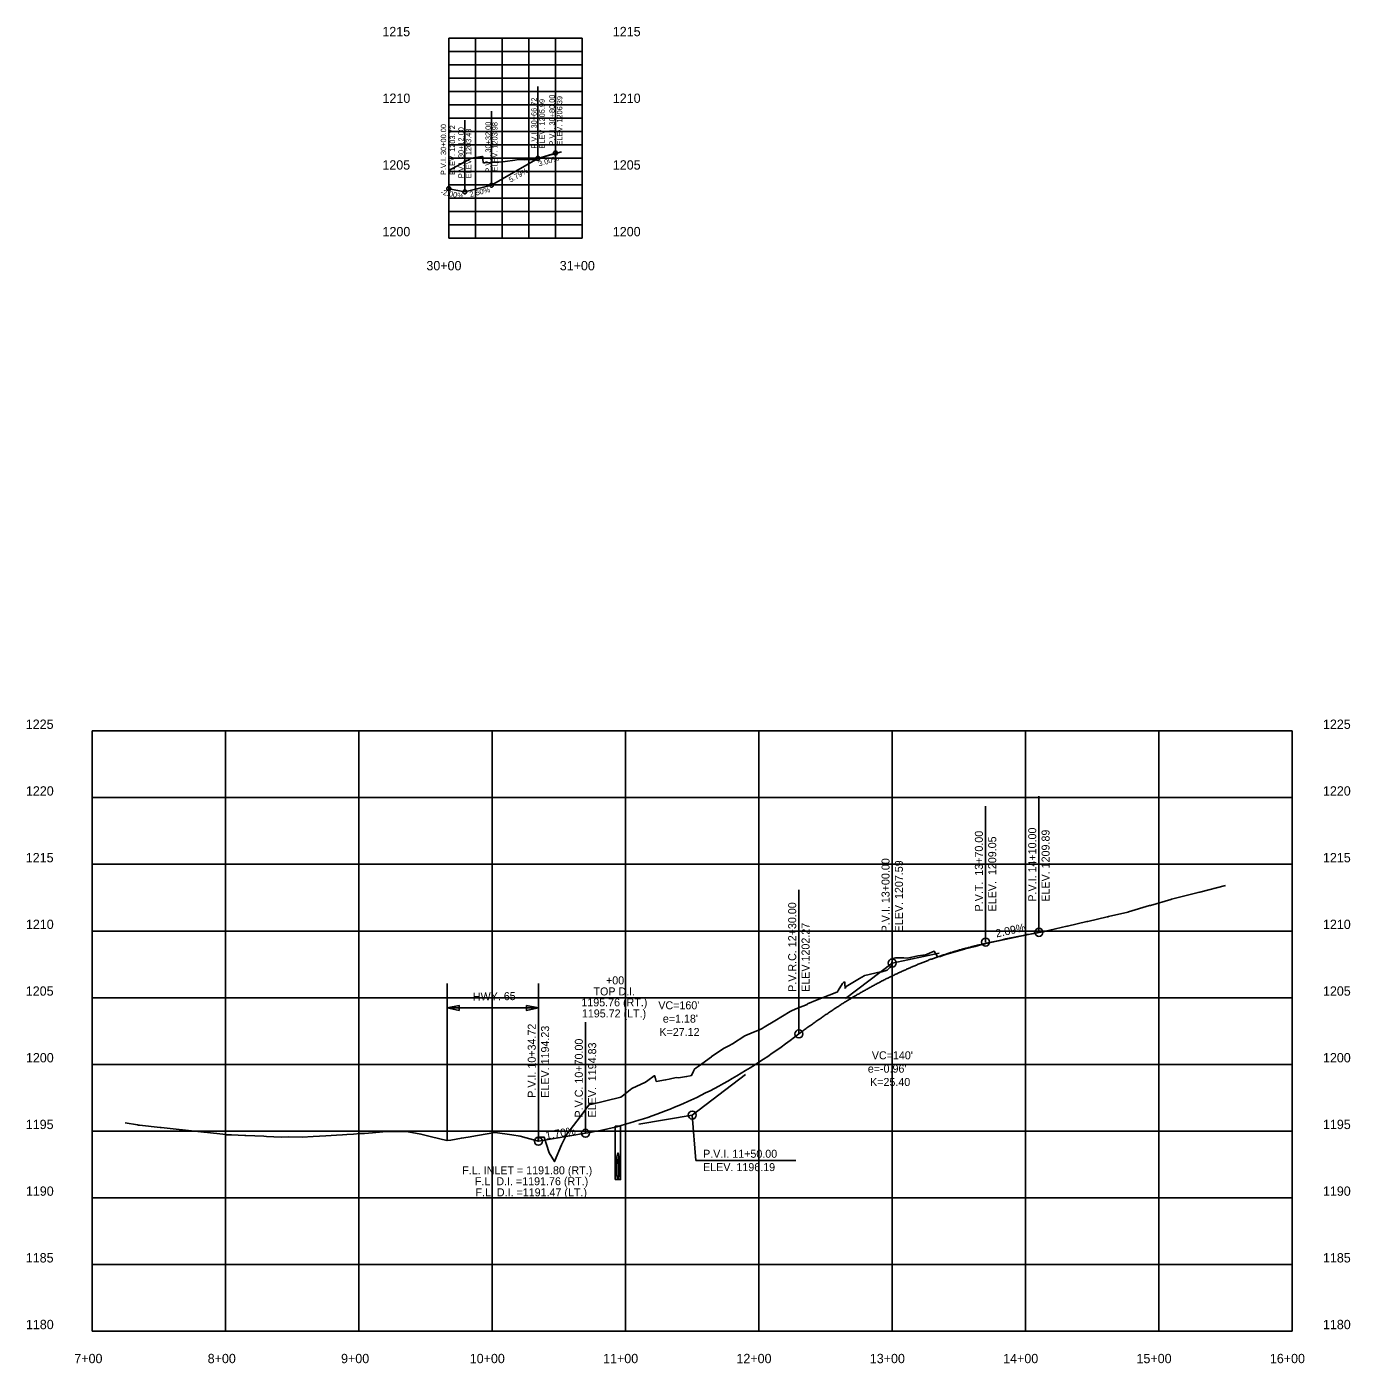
# Model space of a CAD drawing. Extents: x 978525 to 979518, y 704757 to 705759.
import ezdxf

# ---------------------------------------------------------------- set-up
doc = ezdxf.new("R2010")
doc.units = 0
for name, color, linetype in [('R_Axis', 7, 'Continuous'), ('R_Axis Annot', 7, 'Continuous'), ('R_Draft', 7, 'Continuous'), ('R_Exist Surface', 7, 'Continuous'), ('R_Grid', 7, 'Continuous'), ('R_Vert Alg', 7, 'Continuous'), ('R_Vert Alg Annot', 7, 'Continuous')]:
    doc.layers.add(name, color=color, linetype=linetype)

msp = doc.modelspace()

# ---------------------------------------------------------------- linework, layer by layer
at = {"layer": 'R_Axis'}
for p, q in [((978841.6, 705600.8), (978841.6, 705750.8)), ((978941.6, 705600.8), (978941.6, 705750.8)), ((978841.6, 705600.8), (978941.6, 705600.8)), ((978574.1, 704781.5), (978574.1, 705231.5)), ((979474.1, 704781.5), (979474.1, 705231.5)), ((978574.1, 704781.5), (979474.1, 704781.5))]:
    msp.add_line(p, q, dxfattribs=at)
at = {"layer": 'R_Draft'}
msp.add_lwpolyline([(978966.4, 704895.1), (978970.4, 704895.1), (978970.4, 704935.1), (978966.4, 704935.1)], close=True, dxfattribs=at)
for centre, major_axis in [((978968.4, 704905.1), (0, -10)), ((978968.4, 704902.6), (0.02, -7.47))]:
    msp.add_ellipse(centre, major_axis=major_axis, ratio=0.1, dxfattribs=at)
at = {"layer": 'R_Exist Surface'}
for points in [[(978841.6, 705651.7), (978858.5, 705660.8), (978866.4, 705662.1), (978866.6, 705662), (978867, 705661.9), (978867.1, 705660), (978867.3, 705657.7), (978867.8, 705657.5), (978868.5, 705657.5), (978868.5, 705657.5), (978876.5, 705657.8), (978879.1, 705657.9), (978883.8, 705658.3), (978891.1, 705659.4), (978893.9, 705659.9), (978898.4, 705659.7), (978903.5, 705659.8), (978905.7, 705659.6), (978906.6, 705659.6), (978906.6, 705659.4), (978907, 705659.6), (978907.2, 705659.9), (978907.2, 705659.7), (978907.3, 705660.2), (978907.8, 705660.9), (978907.9, 705660.9), (978908.2, 705660.9), (978908.3, 705660.7), (978926.2, 705665.7)], [(978599, 704937.6), (978608.1, 704936.1), (978608.8, 704936), (978609.6, 704935.9), (978625.2, 704934.2), (978625.9, 704934.1), (978641.7, 704932.4), (978641.8, 704932.4), (978657.9, 704930.7), (978658.4, 704930.6), (978674.5, 704928.9), (978674.8, 704928.8), (978678.6, 704928.7), (978688.7, 704928.3), (978689.3, 704928.2), (978702.8, 704927.6), (978704.9, 704927.5), (978715.9, 704927), (978721.4, 704927.2), (978731.6, 704926.9), (978740, 704927.4), (978749.3, 704927.9), (978757.4, 704928.5), (978761.9, 704928.7), (978765.2, 704929), (978770.2, 704929.3), (978774.8, 704929.6), (978778.4, 704929.8), (978784.5, 704930.3), (978786.7, 704930.5), (978786.8, 704930.5), (978795, 704931.2), (978795.4, 704931.2), (978795.4, 704931.2), (978809.9, 704931.1), (978811.1, 704931), (978820.7, 704929.2), (978828.6, 704927.2), (978840.2, 704924.5), (978840.4, 704924.4), (978843, 704924.6), (978851, 704926.2), (978856.1, 704927), (978863, 704928.1), (978876, 704930.4), (978876.3, 704930.4), (978876.4, 704930.4), (978888.9, 704928.6), (978895.2, 704927.6), (978906.9, 704924.4), (978908.6, 704923.9), (978908.6, 704924.2), (978908.6, 704927.2), (978909.1, 704927.2), (978909.1, 704927.2), (978909.4, 704927), (978913.2, 704926.9), (978916.8, 704915.3), (978920.9, 704908.6), (978926, 704921.1), (978930.2, 704929.2), (978940.1, 704942.3), (978947.1, 704951.6), (978948.2, 704951.5), (978970.7, 704956.9), (978971.6, 704957.7), (978975.1, 704960.4), (978978.9, 704963.4), (978989.2, 704968.1), (978990.9, 704969.4), (978995.6, 704972.8), (978996.1, 704972.8), (978996.2, 704971.9), (978996.2, 704972.8), (978996.4, 704971.9), (978997.1, 704968.7), (979004.1, 704969.8), (979006.8, 704970.4), (979012.2, 704971.6), (979013.9, 704971.5), (979019.9, 704972.4), (979022.6, 704973), (979023.7, 704973.2), (979025, 704976.4), (979025.8, 704978), (979027.1, 704978.8), (979028.6, 704979.9), (979038.5, 704987.2), (979038.7, 704987.4), (979048.2, 704993.6), (979051.7, 704995.5), (979054.3, 704996.9), (979054.4, 704996.9), (979063.7, 705002.8), (979070.2, 705005.6), (979074.5, 705007.4), (979076.6, 705008.5), (979078.2, 705009.4), (979086.1, 705014.2), (979097.6, 705021.1), (979098.1, 705021.5), (979101.9, 705023.2), (979110.2, 705026.5), (979110.6, 705026.8), (979117.8, 705029.8), (979126.8, 705033.4), (979131.4, 705035.1), (979133.1, 705035.9), (979133.6, 705036.8), (979136.7, 705042.1), (979137.8, 705043.2), (979138.1, 705043.3), (979138.4, 705043.2), (979138.4, 705043.2), (979138.5, 705043.3), (979138.6, 705042), (979138.8, 705038.6), (979139.1, 705039), (979139.5, 705039.9), (979149.5, 705045.9), (979153.1, 705048), (979153.3, 705048.1), (979153.4, 705048.1), (979153.4, 705048.1), (979153.5, 705048.2), (979165.3, 705050.8), (979166.2, 705051), (979170.4, 705052.2), (979172.2, 705054.1), (979173.5, 705054.8), (979173.9, 705057.9), (979174.4, 705061), (979176.6, 705061.5), (979180.3, 705061.5), (979181.2, 705061.4), (979182.8, 705061.3), (979185.3, 705061.2), (979187.9, 705061.6), (979193.4, 705062.8), (979197, 705063.3), (979198.6, 705063.5), (979205.5, 705066.4), (979207.1, 705063.8), (979208, 705062.2), (979209.9, 705062.4), (979210.4, 705062.5), (979212.9, 705063.3), (979212.9, 705063.4), (979214.4, 705063.8), (979228.4, 705068), (979228.8, 705068.1), (979236.4, 705070), (979243.9, 705072.1), (979244.6, 705072.3), (979255.8, 705074.7), (979259.4, 705075.6), (979260.5, 705075.8), (979273.5, 705078.4), (979274.9, 705078.8), (979276.3, 705079), (979289.7, 705081.5), (979290.4, 705081.7), (979292.2, 705082.1), (979305, 705085), (979305.5, 705085.2), (979320.1, 705088.5), (979320.7, 705088.7), (979335.3, 705092), (979335.8, 705092.2), (979336.3, 705092.3), (979350.9, 705095.7), (979351.4, 705095.8), (979367, 705100.5), (979367.9, 705100.7), (979383, 705105.2), (979383.4, 705105.3), (979403.5, 705110.4), (979404.8, 705110.7), (979424.1, 705115.6)]]:
    msp.add_lwpolyline(points, dxfattribs=at)
at = {"layer": 'R_Grid'}
for p, q in [((978841.6, 705750.8), (978941.6, 705750.8)), ((978841.6, 705750.8), (978941.6, 705750.8)), ((978861.6, 705600.8), (978861.6, 705750.8)), ((978881.6, 705600.8), (978881.6, 705750.8)), ((978901.6, 705600.8), (978901.6, 705750.8)), ((978921.6, 705600.8), (978921.6, 705750.8)), ((978841.6, 705740.8), (978941.6, 705740.8)), ((978841.6, 705730.8), (978941.6, 705730.8)), ((978841.6, 705720.8), (978941.6, 705720.8)), ((978841.6, 705710.8), (978941.6, 705710.8)), ((978841.6, 705700.8), (978941.6, 705700.8)), ((978841.6, 705690.8), (978941.6, 705690.8)), ((978841.6, 705680.8), (978941.6, 705680.8)), ((978841.6, 705670.8), (978941.6, 705670.8)), ((978841.6, 705660.8), (978941.6, 705660.8)), ((978841.6, 705650.8), (978941.6, 705650.8)), ((978841.6, 705640.8), (978941.6, 705640.8)), ((978841.6, 705630.8), (978941.6, 705630.8)), ((978841.6, 705620.8), (978941.6, 705620.8)), ((978841.6, 705610.8), (978941.6, 705610.8)), ((978574.1, 705231.5), (979474.1, 705231.5)), ((978674.1, 704781.5), (978674.1, 705231.5)), ((978774.1, 704781.5), (978774.1, 705231.5)), ((978874.1, 704781.5), (978874.1, 705231.5)), ((978974.1, 704781.5), (978974.1, 705231.5)), ((979074.1, 704781.5), (979074.1, 705231.5)), ((979174.1, 704781.5), (979174.1, 705231.5)), ((979274.1, 704781.5), (979274.1, 705231.5)), ((979374.1, 704781.5), (979374.1, 705231.5)), ((978574.1, 705181.5), (979474.1, 705181.5)), ((978574.1, 705131.5), (979474.1, 705131.5)), ((978574.1, 705081.5), (979474.1, 705081.5)), ((978574.1, 705031.5), (979474.1, 705031.5)), ((978574.1, 704981.5), (979474.1, 704981.5)), ((978574.1, 704931.5), (979474.1, 704931.5)), ((978574.1, 704881.5), (979474.1, 704881.5)), ((978574.1, 704831.5), (979474.1, 704831.5))]:
    msp.add_line(p, q, dxfattribs=at)
at = {"layer": 'R_Vert Alg'}
for p, q in [((978908.3, 705660.7), (978908.3, 705714.6)), ((978921.6, 705664.7), (978921.6, 705715.9)), ((978841.6, 705638), (978841.6, 705694.8)), ((978853.6, 705635.6), (978853.6, 705689.3)), ((978873.6, 705640.6), (978873.6, 705696)), ((978873.6, 705640.6), (978908.3, 705660.7)), ((978908.3, 705660.7), (978921.6, 705664.7)), ((978841.6, 705638), (978853.6, 705635.6)), ((978853.6, 705635.6), (978873.6, 705640.6)), ((979284.1, 705080.5), (979284.1, 705182.5)), ((979244.1, 705073.2), (979244.1, 705175.2)), ((979174.1, 705057.5), (979174.1, 705153.5)), ((979104.1, 705004.3), (979104.1, 705112.3)), ((979244.4, 705072.2), (979284.5, 705080.6)), ((979139.1, 705030.9), (979174.1, 705057.5)), ((979174.1, 705057.5), (979209.2, 705064.8)), ((978840.4, 705042.2), (978840.4, 704924.4)), ((978908.8, 704923.9), (978908.8, 705042.2)), ((978944.1, 704929.9), (978944.1, 705013.2)), ((979024.1, 704943.5), (979064.1, 704973.9)), ((978984.1, 704936.7), (979024.1, 704943.5)), ((979026.9, 704909.5), (979024.1, 704943.5)), ((978908.8, 704923.9), (978944.1, 704929.9)), ((979101.7, 704909.5), (979026.9, 704909.5))]:
    msp.add_line(p, q, dxfattribs=at)
msp.add_lwpolyline([(978944.1, 704929.9), (978947.5, 704930.5), (978950.8, 704931.1), (978954.1, 704931.8), (978957.5, 704932.5), (978960.8, 704933.2), (978964.1, 704934), (978967.5, 704934.8), (978970.8, 704935.7), (978974.1, 704936.6), (978977.5, 704937.6), (978980.8, 704938.6), (978984.1, 704939.6), (978987.5, 704940.7), (978990.8, 704941.8), (978994.1, 704943), (978997.5, 704944.2), (979000.8, 704945.4), (979004.1, 704946.7), (979007.5, 704948), (979010.8, 704949.4), (979014.1, 704950.8), (979017.5, 704952.2), (979020.8, 704953.7), (979027.5, 704956.8), (979030.8, 704958.4), (979034.1, 704960.1), (979037.5, 704961.8), (979040.8, 704963.5), (979044.1, 704965.3), (979047.5, 704967.1), (979050.8, 704969), (979054.1, 704970.9), (979057.5, 704972.8), (979060.8, 704974.8), (979064.1, 704976.8), (979067.5, 704978.9), (979070.8, 704981), (979074.1, 704983.1), (979077.5, 704985.3), (979080.8, 704987.5), (979084.1, 704989.8), (979087.5, 704992.1), (979090.8, 704994.5), (979094.1, 704996.9), (979097.5, 704999.3), (979100.8, 705001.8), (979104.1, 705004.3)], dxfattribs=at)
for centre, radius in [((978908.3, 705660.7), 1.5), ((978921.6, 705664.7), 1.5), ((978841.6, 705638), 1.5), ((978853.6, 705635.6), 1.5), ((978873.6, 705640.6), 1.5), ((979244.1, 705073.2), 3), ((979284.1, 705080.5), 3), ((979174.1, 705057.5), 3), ((979104.1, 705004.3), 3), ((979024.1, 704943.5), 3), ((978908.8, 704923.9), 3), ((978944.1, 704929.9), 3)]:
    msp.add_circle(centre, radius, dxfattribs=at)
msp.add_spline([(979244.1, 705072.1), (979241.4, 705071.5), (979238.7, 705070.9), (979236, 705070.3), (979233.4, 705069.6), (979230.7, 705068.9), (979228, 705068.2), (979225.3, 705067.5), (979222.6, 705066.7), (979219.9, 705065.9), (979217.2, 705065.1), (979214.5, 705064.2), (979211.8, 705063.3), (979209.1, 705062.4), (979206.4, 705061.4), (979203.7, 705060.5), (979201, 705059.5), (979198.4, 705058.4), (979195.7, 705057.4), (979193, 705056.3), (979190.3, 705055.1), (979187.6, 705054), (979184.9, 705052.8), (979182.2, 705051.6), (979179.5, 705050.4), (979176.8, 705049.1), (979174.1, 705047.8), (979171.4, 705046.5), (979168.7, 705045.2), (979166, 705043.8), (979163.4, 705042.4), (979160.7, 705040.9), (979158, 705039.5), (979155.3, 705038), (979152.6, 705036.5), (979149.9, 705034.9), (979147.2, 705033.4), (979144.5, 705031.8), (979141.8, 705030.1), (979139.1, 705028.5), (979136.4, 705026.8), (979133.7, 705025), (979131, 705023.3), (979128.4, 705021.5), (979125.7, 705019.7), (979123, 705017.9), (979120.3, 705016), (979117.6, 705014.1), (979114.9, 705012.2), (979112.2, 705010.3), (979109.5, 705008.3), (979106.8, 705006.3), (979104.1, 705004.3)], degree=3, dxfattribs=at)
at = {"layer": 'R_Vert Alg Annot'}
msp.add_line((978840.4, 705023.8), (978908.8, 705023.8), dxfattribs=at)
for points in [[(978849.4, 705022), (978840.4, 705023.8), (978849.4, 705025.6)], [(978899.8, 705025.6), (978908.8, 705023.8), (978899.8, 705022)]]:
    msp.add_lwpolyline(points, close=True, dxfattribs=at)

# ---------------------------------------------------------------- texts
at = {"layer": 'R_Axis Annot'}
for s, p in [('1215', (978791.8, 705752.3)), ('1215', (978791.8, 705752.3)), ('1215', (978964.6, 705752.3)), ('1215', (978964.6, 705752.3)), ('1210', (978791.9, 705702.3)), ('1210', (978964.6, 705702.3)), ('1205', (978791.8, 705652.3)), ('1205', (978964.6, 705652.3)), ('1200', (978791.9, 705602.3)), ('1200', (978964.6, 705602.3)), ('30+00', (978824.8, 705576.8)), ('31+00', (978924.8, 705576.8)), ('1225', (978524.4, 705233)), ('1225', (979497.1, 705233)), ('1220', (978524.5, 705183)), ('1220', (979497.1, 705183)), ('1215', (978524.4, 705133)), ('1215', (979497.1, 705133)), ('1210', (978524.5, 705083)), ('1210', (979497.1, 705083)), ('1205', (978524.4, 705033)), ('1205', (979497.1, 705033)), ('1200', (978524.5, 704983)), ('1200', (979497.1, 704983)), ('1195', (978524.4, 704933)), ('1195', (979497.1, 704933)), ('1190', (978524.5, 704883)), ('1190', (979497.1, 704883)), ('1185', (978524.4, 704833)), ('1185', (979497.1, 704833)), ('1180', (978524.5, 704783)), ('1180', (979497.1, 704783)), ('7+00', (978560.8, 704757.5)), ('8+00', (978660.8, 704757.5)), ('9+00', (978760.8, 704757.5)), ('10+00', (978857.3, 704757.5)), ('11+00', (978957.3, 704757.5)), ('12+00', (979057.3, 704757.5)), ('13+00', (979157.3, 704757.5)), ('14+00', (979257.3, 704757.5)), ('15+00', (979357.3, 704757.5)), ('16+00', (979457.3, 704757.5))]:
    msp.add_text(s, height=7, dxfattribs=at).set_placement(p)
at = {"layer": 'R_Vert Alg Annot'}
for s, height, rotation, p in [('P.V.I. 30+80.00', 4, 90, (978921, 705670.3)), ('P.V.I. 30+66.72', 4, 90, (978907.5, 705668.1)), ('ELEV. 1205.99', 4, 90, (978913.5, 705668.1)), ('ELEV. 1206.39', 4, 90, (978926.7, 705670.3)), ('P.V.I. 30+32.00', 4, 90, (978873.1, 705650)), ('ELEV. 1203.98', 4, 90, (978878.1, 705650.8)), ('P.V.I. 30+00.00', 4, 90, (978839.6, 705648.2)), ('ELEV. 1203.72', 4, 90, (978846.3, 705648.4)), ('P.V.I. 30+12.00', 4, 90, (978852.8, 705645.9)), ('ELEV. 1203.48', 4, 90, (978858.4, 705645.9)), ('3.00%', 4, 16.6992, (978909.4, 705654.6)), ('5.79%', 4, 30.06, (978888, 705642.5)), ('-2.00%', 4, 348.6901, (978835.1, 705633.7)), ('2.50%', 4, 14.0362, (978857.7, 705631.7)), ('P.V.T.  13+70.00', 6, 90, (979242.1, 705096.2)), ('P.V.I. 14+10.00', 6, 90, (979282.1, 705103.5)), ('ELEV. 1209.89', 6, 90, (979292.1, 705103.5)), ('ELEV.  1209.05', 6, 90, (979252.1, 705096.2)), ('P.V.I. 13+00.00', 6, 90, (979172.1, 705080.5)), ('ELEV. 1207.59', 6, 90, (979182.1, 705080.5)), ('P.V.R.C. 12+30.00', 6, 90, (979102.1, 705035.9)), ('ELEV.1202.27', 6, 90, (979112.1, 705035.9)), ('2.09%', 6, 12.6995, (979252.3, 705076.6)), ('HWY. 65', 6, 0.7432, (978859.7, 705029.3)), ('P.V.I. 10+34.72', 6, 90, (978906.8, 704956.5)), ('ELEV. 1194.23', 6, 90, (978916.8, 704956.5)), ('P.V.C. 10+70.00', 6, 90, (978942.1, 704941.7)), ('ELEV.  1194.83', 6, 90, (978952.1, 704941.7)), ('1.70%', 6, 9.648, (978914.6, 704925.2))]:
    msp.add_text(s, height=height, rotation=rotation, dxfattribs=at).set_placement(p)
for s, p in [('+00', (978959.5, 705041.5)), ('TOP D.I.', (978950.1, 705033.2)), ('1195.76 (RT.)', (978941, 705025)), ("VC=160'", (978998.7, 705022.8)), ('1195.72 (LT.)', (978941.4, 705016.7)), ("e=1.18'", (979002.1, 705012.8)), ('K=27.12', (978999.5, 705002.8)), ("VC=140'", (979158.8, 704985.3)), ("e=-0.96'", (979155.8, 704975.3)), ('K=25.40', (979157.5, 704965.3)), ('P.V.I. 11+50.00', (979032.3, 704911.5)), ('F.L. INLET = 1191.80 (RT.)', (978851.7, 704899.1)), ('ELEV. 1196.19', (979032.3, 704901.5)), ('F.L. D.I. =1191.76 (RT.)', (978861.2, 704890.9)), ('F.L. D.I. =1191.47 (LT.)', (978861.6, 704882.6))]:
    msp.add_text(s, height=6, dxfattribs=at).set_placement(p)

doc.saveas('drawing.dxf')
